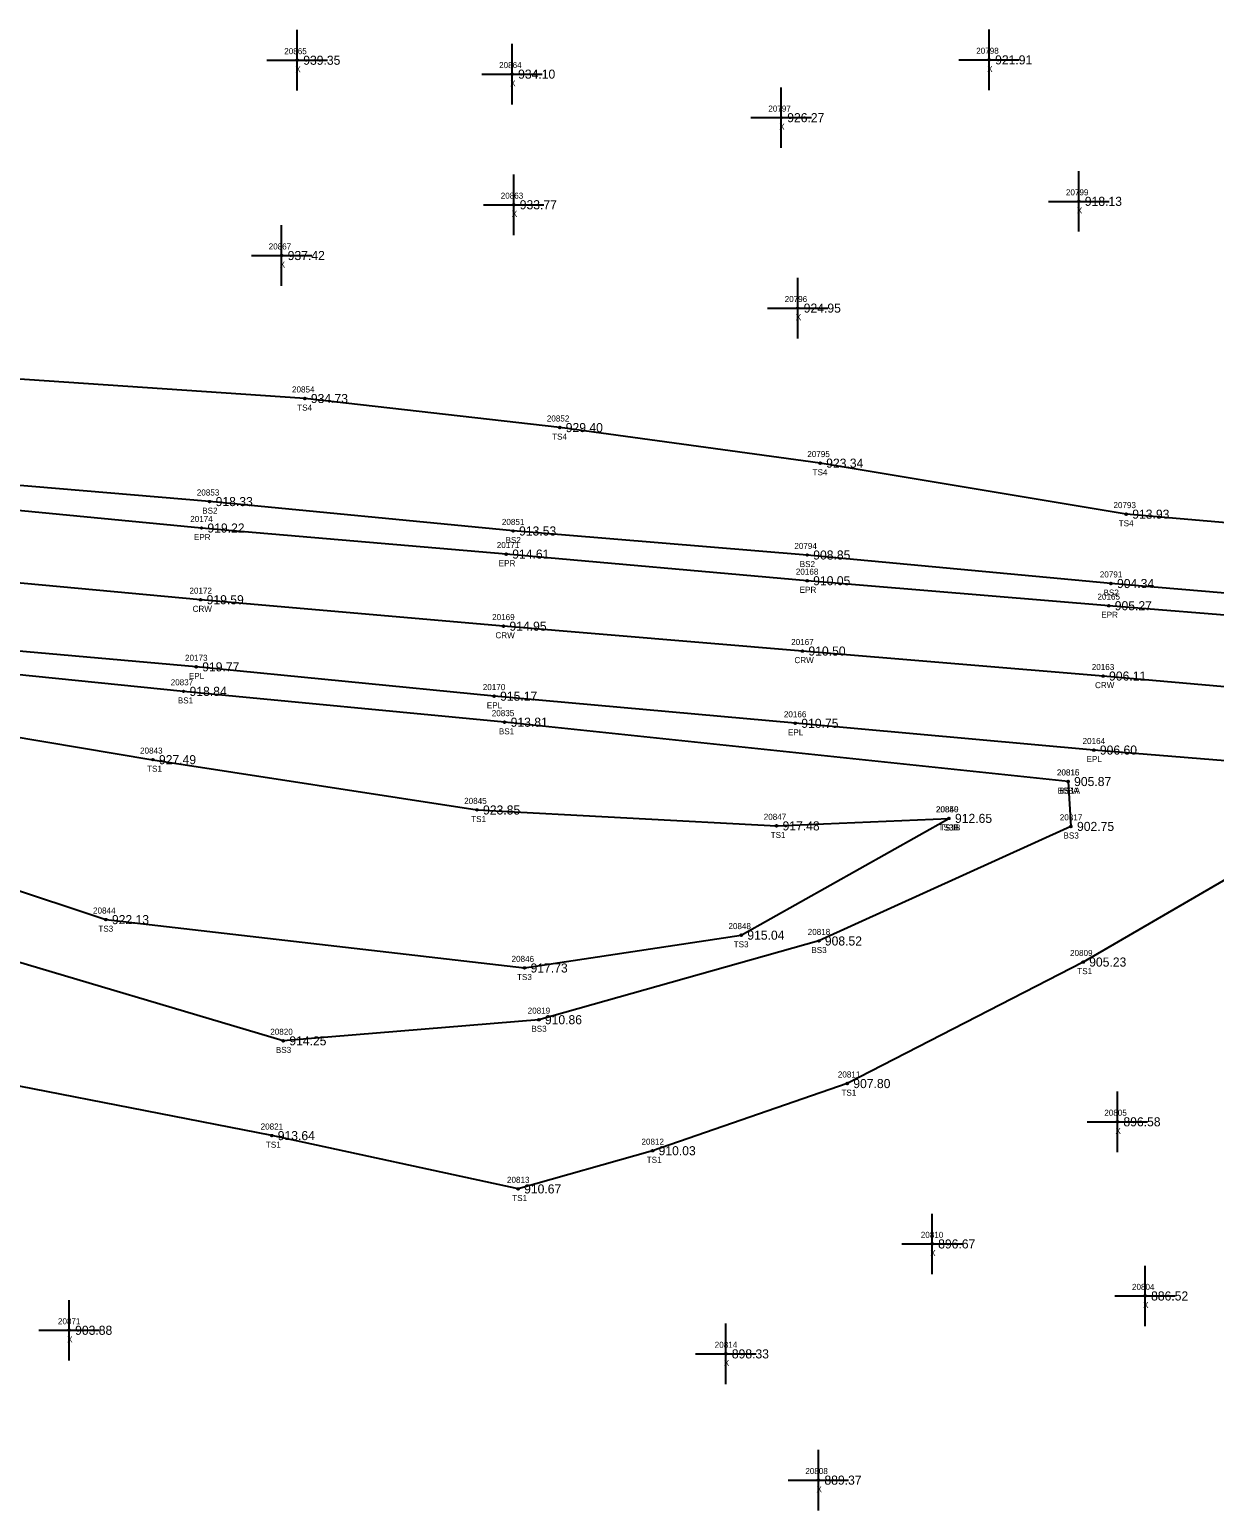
# Model space of a CAD drawing. Extents: x 1394668 to 1397182, y 1073212 to 1074501.
# Drawn here: x 1394844.2 to 1395039.9, y 1073234.9 to 1073479.6 of the extents above; entities that cross this region are included whole.
import ezdxf

# ---------------------------------------------------------------- set-up
doc = ezdxf.new("R2010")
doc.units = 0
for name, color, linetype in [('RD_DTM_BkLn1', 7, 'Continuous'), ('RD_DTM_BkLn2', 7, 'Continuous'), ('RD_DTM_BkLn_txCode', 7, 'Continuous'), ('RD_EX_Misc', 7, 'Continuous'), ('RD_EX_Misc_txCode', 7, 'Continuous'), ('RD_EX_Road', 7, 'Continuous'), ('RD_EX_Road_txCode', 7, 'Continuous'), ('RD_EX_TX_Misc_ELEV', 7, 'Continuous'), ('RD_EX_TX_Road_ELEV', 7, 'Continuous'), ('RD_HC_Survey_ELEV', 7, 'Continuous'), ('RD_HC_Survey_txCode', 7, 'Continuous'), ('RD_SMD_Locator', 7, 'Continuous')]:
    doc.layers.add(name, color=color, linetype=linetype)

msp = doc.modelspace()

# ---------------------------------------------------------------- linework, layer by layer
at = {"layer": 'RD_DTM_BkLn1'}
msp.add_lwpolyline([(1395269.86, 1073375.63), (1395220.56, 1073368.3), (1395170.5, 1073365.12), (1395120.93, 1073365.32), (1395071.05, 1073368.42), (1395021.54, 1073372.81), (1394971.87, 1073376.94), (1394922.47, 1073381.05), (1394872.44, 1073385.42), (1394823.01, 1073389.97), (1394773.09, 1073394.98), (1394723.98, 1073400.02), (1394673.96, 1073406.13)], dxfattribs=at)
at = {"layer": 'RD_DTM_BkLn2'}
for points in [[(1395114.77, 1073459.28), (1395092.12, 1073431.75), (1395067.87, 1073399.99), (1395061.04, 1073396.47), (1395025.37, 1073399.56), (1394974.8, 1073407.99), (1394931.77, 1073413.87), (1394889.66, 1073418.67), (1394830.32, 1073422.7), (1394776.13, 1073426.07), (1394727.84, 1073425.98), (1394677.73, 1073438.51)], [(1395071.67, 1073383.99), (1395022.85, 1073388.1), (1394972.66, 1073392.81), (1394924.06, 1073396.78), (1394873.93, 1073401.64), (1394823.64, 1073405.87), (1394773.54, 1073410.91), (1394725.43, 1073416.05), (1394673.91, 1073423.25)], [(1394670.94, 1073391.19), (1394739.49, 1073383.51), (1394739.49, 1073383.51), (1394765.8, 1073375.46), (1394810.45, 1073368.06), (1394864.56, 1073358.99), (1394918.11, 1073350.68), (1394967.59, 1073348.05), (1394996.08, 1073349.29)], [(1394739.49, 1073383.51), (1394764.94, 1073371.86), (1394804.66, 1073349.89), (1394856.79, 1073332.56), (1394925.96, 1073324.57), (1394961.77, 1073329.99), (1394996.08, 1073349.29)], [(1395015.76, 1073355.38), (1394922.67, 1073365.18), (1394869.62, 1073370.28), (1394820.24, 1073375.25), (1394747.09, 1073382.96)], [(1395065.07, 1073345.12), (1395048.86, 1073343.34), (1395018.25, 1073325.55), (1394979.28, 1073305.47), (1394947.11, 1073294.37), (1394924.89, 1073288.06), (1394884.19, 1073296.87), (1394821.51, 1073309.12), (1394774.98, 1073327.05), (1394739.84, 1073344.19), (1394711.9, 1073363.27), (1394701.45, 1073376.62)], [(1395015.76, 1073355.38), (1395016.24, 1073347.96), (1394974.58, 1073329.03), (1394928.32, 1073316.02), (1394886.1, 1073312.53), (1394835.64, 1073327.51), (1394785.59, 1073349.09), (1394745.24, 1073368.83), (1394701.45, 1073376.62)]]:
    msp.add_lwpolyline(points, dxfattribs=at)
at = {"layer": 'RD_EX_Misc'}
for p, q in [((1394888.4, 1073469.57), (1394888.4, 1073479.57)), ((1394923.9, 1073467.27), (1394923.9, 1073477.27)), ((1395002.71, 1073469.63), (1395002.71, 1073479.63)), ((1394883.4, 1073474.57), (1394893.4, 1073474.57)), ((1394997.71, 1073474.63), (1395007.71, 1073474.63)), ((1394918.9, 1073472.27), (1394928.9, 1073472.27)), ((1394968.36, 1073460.08), (1394968.36, 1073470.08)), ((1394963.36, 1073465.08), (1394973.36, 1073465.08)), ((1394924.17, 1073445.69), (1394924.17, 1073455.69)), ((1395017.53, 1073446.25), (1395017.53, 1073456.25)), ((1394919.17, 1073450.69), (1394929.17, 1073450.69)), ((1395012.53, 1073451.25), (1395022.53, 1073451.25)), ((1394885.83, 1073437.3), (1394885.83, 1073447.3)), ((1394880.83, 1073442.3), (1394890.83, 1073442.3)), ((1394971.09, 1073428.61), (1394971.09, 1073438.61)), ((1394966.09, 1073433.61), (1394976.09, 1073433.61)), ((1395023.91, 1073294.15), (1395023.91, 1073304.15)), ((1395018.91, 1073299.15), (1395028.91, 1073299.15)), ((1394993.3, 1073273.97), (1394993.3, 1073283.97)), ((1394988.3, 1073278.97), (1394998.3, 1073278.97)), ((1395028.48, 1073265.37), (1395028.48, 1073275.37)), ((1394850.71, 1073259.7), (1394850.71, 1073269.7)), ((1395023.48, 1073270.37), (1395033.48, 1073270.37)), ((1394845.71, 1073264.7), (1394855.71, 1073264.7)), ((1394959.21, 1073255.8), (1394959.21, 1073265.8)), ((1394954.21, 1073260.8), (1394964.21, 1073260.8)), ((1394974.51, 1073234.94), (1394974.51, 1073244.94)), ((1394969.51, 1073239.94), (1394979.51, 1073239.94))]:
    msp.add_line(p, q, dxfattribs=at)
at = {"layer": 'RD_EX_Road'}
for points in [[(1395267.16, 1073387.31), (1395218.96, 1073380.11), (1395169.59, 1073377.09), (1395120.52, 1073377.31), (1395071.75, 1073380.45), (1395022.48, 1073384.43), (1394972.65, 1073388.56), (1394922.93, 1073392.96), (1394872.57, 1073397.27), (1394823.93, 1073401.93), (1394774.03, 1073406.64), (1394724.37, 1073412.09), (1394676.23, 1073417.71)], [(1395271.04, 1073363.5), (1395222.14, 1073356.32), (1395170.34, 1073352.86), (1395119.91, 1073353.35), (1395070.19, 1073356.5), (1395020.02, 1073360.58), (1394970.69, 1073365), (1394920.93, 1073369.48), (1394871.71, 1073374.33), (1394821.21, 1073378.78), (1394772.49, 1073383.81), (1394722.62, 1073388.78), (1394672.88, 1073394.93)]]:
    msp.add_lwpolyline(points, dxfattribs=at)
at = {"layer": 'RD_SMD_Locator'}
for centre in [(1394888.4, 1073474.57), (1394923.9, 1073472.27), (1395002.71, 1073474.63), (1394968.36, 1073465.08), (1394924.17, 1073450.69), (1395017.53, 1073451.25), (1394885.83, 1073442.3), (1394971.09, 1073433.61), (1394889.66, 1073418.67), (1394931.77, 1073413.87), (1394974.8, 1073407.99), (1394873.93, 1073401.64), (1395025.37, 1073399.56), (1394872.57, 1073397.27), (1394924.06, 1073396.78), (1394922.93, 1073392.96), (1394972.66, 1073392.81), (1394972.65, 1073388.56), (1395022.85, 1073388.1), (1394872.44, 1073385.42), (1395022.48, 1073384.43), (1394922.47, 1073381.05), (1394971.87, 1073376.94), (1394871.71, 1073374.33), (1395021.54, 1073372.81), (1394869.62, 1073370.28), (1394920.93, 1073369.48), (1394922.67, 1073365.18), (1394970.69, 1073365), (1395020.02, 1073360.58), (1394864.56, 1073358.99), (1395015.76, 1073355.38), (1395015.76, 1073355.38), (1394918.11, 1073350.68), (1394967.59, 1073348.05), (1394996.08, 1073349.29), (1394996.08, 1073349.29), (1395016.24, 1073347.96), (1394856.79, 1073332.56), (1394961.77, 1073329.99), (1394974.58, 1073329.03), (1395018.25, 1073325.55), (1394925.96, 1073324.57), (1394928.32, 1073316.02), (1394886.1, 1073312.53), (1394979.28, 1073305.47), (1395023.91, 1073299.15), (1394884.19, 1073296.87), (1394947.11, 1073294.37), (1394924.89, 1073288.06), (1394993.3, 1073278.97), (1395028.48, 1073270.37), (1394850.71, 1073264.7), (1394959.21, 1073260.8), (1394974.51, 1073239.94)]:
    msp.add_circle(centre, 0.15, dxfattribs=at)

# ---------------------------------------------------------------- texts
at = {"layer": 'RD_DTM_BkLn_txCode'}
for s, p in [('20854', (1394887.54, 1073419.67)), ('TS4', (1394888.41, 1073416.67)), ('20852', (1394929.65, 1073414.87)), ('TS4', (1394930.52, 1073411.87)), ('20795', (1394972.68, 1073408.99)), ('TS4', (1394973.56, 1073405.99)), ('20853', (1394871.82, 1073402.64)), ('20793', (1395023.26, 1073400.56)), ('BS2', (1394872.71, 1073399.64)), ('20851', (1394922.22, 1073397.78)), ('TS4', (1395024.13, 1073397.56)), ('BS2', (1394922.83, 1073394.78)), ('20794', (1394970.54, 1073393.81)), ('BS2', (1394971.43, 1073390.81)), ('20791', (1395021.01, 1073389.1)), ('BS2', (1395021.62, 1073386.1)), ('20837', (1394867.5, 1073371.28)), ('BS1', (1394868.68, 1073368.28)), ('20835', (1394920.55, 1073366.18)), ('BS1', (1394921.72, 1073363.18)), ('20843', (1394862.44, 1073359.99)), ('TS1', (1394863.6, 1073356.99)), ('20816', (1395013.91, 1073356.38)), ('20815', (1395013.93, 1073356.38)), ('20845', (1394915.99, 1073351.68)), ('BS3A', (1395014.05, 1073353.38)), ('BS1A', (1395014.33, 1073353.38)), ('20847', (1394965.48, 1073349.05)), ('20850', (1394993.92, 1073350.29)), ('20849', (1394993.96, 1073350.29)), ('TS1', (1394917.15, 1073348.68)), ('TS3B', (1394994.37, 1073347.29)), ('TS1B', (1394994.65, 1073347.29)), ('20817', (1395014.4, 1073348.96)), ('TS1', (1394966.63, 1073346.05)), ('BS3', (1395015.01, 1073345.96)), ('20844', (1394854.67, 1073333.56)), ('TS3', (1394855.55, 1073330.56)), ('20848', (1394959.65, 1073330.99)), ('20818', (1394972.75, 1073330.03)), ('TS3', (1394960.52, 1073327.99)), ('BS3', (1394973.35, 1073327.03)), ('20846', (1394923.82, 1073325.57)), ('20809', (1395016.09, 1073326.55)), ('TS3', (1394924.72, 1073322.57)), ('TS1', (1395017.29, 1073323.55)), ('20819', (1394926.48, 1073317.02)), ('20820', (1394883.95, 1073313.53)), ('BS3', (1394927.09, 1073314.02)), ('BS3', (1394884.88, 1073310.53)), ('20811', (1394977.73, 1073306.47)), ('TS1', (1394978.32, 1073303.47)), ('20821', (1394882.36, 1073297.87)), ('20812', (1394945.28, 1073295.37)), ('TS1', (1394883.23, 1073294.87)), ('TS1', (1394946.15, 1073292.37)), ('20813', (1394923.06, 1073289.06)), ('TS1', (1394923.93, 1073286.06))]:
    msp.add_text(s, height=1, dxfattribs=at).set_placement(p)
at = {"layer": 'RD_EX_Misc_txCode'}
for s, p in [('20865', (1394886.26, 1073475.57)), ('20798', (1395000.59, 1073475.63)), ('X', (1394888.09, 1073472.57)), ('20864', (1394921.76, 1073473.27)), ('X', (1395002.4, 1073472.63)), ('X', (1394923.59, 1073470.27)), ('20797', (1394966.24, 1073466.08)), ('X', (1394968.04, 1073463.08)), ('20799', (1395015.41, 1073452.25)), ('20863', (1394922.03, 1073451.69)), ('X', (1394923.85, 1073448.69)), ('X', (1395017.21, 1073449.25)), ('20867', (1394883.69, 1073443.3)), ('X', (1394885.51, 1073440.3)), ('20796', (1394968.94, 1073434.61)), ('X', (1394970.77, 1073431.61)), ('20805', (1395021.75, 1073300.15)), ('X', (1395023.59, 1073297.15)), ('20810', (1394991.43, 1073279.97)), ('X', (1394992.99, 1073276.97)), ('20804', (1395026.32, 1073271.37)), ('X', (1395028.16, 1073268.37)), ('20871', (1394848.87, 1073265.7)), ('X', (1394850.39, 1073262.7)), ('20814', (1394957.38, 1073261.8)), ('X', (1394958.9, 1073258.8)), ('20808', (1394972.35, 1073240.94)), ('X', (1394974.2, 1073237.94))]:
    msp.add_text(s, height=1, dxfattribs=at).set_placement(p)
at = {"layer": 'RD_EX_Road_txCode'}
for s, p in [('20174', (1394870.73, 1073398.27)), ('EPR', (1394871.34, 1073395.27)), ('20171', (1394921.38, 1073393.96)), ('EPR', (1394921.7, 1073390.96)), ('20168', (1394970.79, 1073389.56)), ('EPR', (1394971.42, 1073386.56)), ('20165', (1395020.62, 1073385.43)), ('EPR', (1395021.25, 1073382.43)), ('20173', (1394869.87, 1073375.33)), ('EPL', (1394870.5, 1073372.33)), ('20170', (1394919.06, 1073370.48)), ('EPL', (1394919.73, 1073367.48)), ('20166', (1394968.81, 1073366)), ('EPL', (1394969.49, 1073363)), ('20164', (1395018.16, 1073361.58)), ('EPL', (1395018.81, 1073358.58))]:
    msp.add_text(s, height=1, dxfattribs=at).set_placement(p)
at = {"layer": 'RD_EX_TX_Misc_ELEV'}
for s, p in [('939.35', (1394889.4, 1073473.82)), ('921.91', (1395003.71, 1073473.88)), ('934.10', (1394924.9, 1073471.52)), ('926.27', (1394969.36, 1073464.33)), ('933.77', (1394925.17, 1073449.94)), ('918.13', (1395018.53, 1073450.5)), ('937.42', (1394886.83, 1073441.55)), ('924.95', (1394972.09, 1073432.86)), ('934.73', (1394890.66, 1073417.92)), ('929.40', (1394932.77, 1073413.12)), ('923.34', (1394975.8, 1073407.24)), ('918.33', (1394874.93, 1073400.89)), ('913.93', (1395026.37, 1073398.81)), ('913.53', (1394925.06, 1073396.03)), ('908.85', (1394973.66, 1073392.06)), ('904.34', (1395023.85, 1073387.35)), ('918.84', (1394870.62, 1073369.53)), ('913.81', (1394923.67, 1073364.43)), ('927.49', (1394865.56, 1073358.24)), ('905.87', (1395016.76, 1073354.63)), ('905.87', (1395016.76, 1073354.63)), ('923.85', (1394919.11, 1073349.93)), ('912.65', (1394997.08, 1073348.54)), ('912.65', (1394997.08, 1073348.54)), ('917.48', (1394968.59, 1073347.3)), ('902.75', (1395017.24, 1073347.21)), ('922.13', (1394857.79, 1073331.81)), ('915.04', (1394962.77, 1073329.24)), ('908.52', (1394975.58, 1073328.28)), ('905.23', (1395019.25, 1073324.8)), ('917.73', (1394926.96, 1073323.82)), ('910.86', (1394929.32, 1073315.27)), ('914.25', (1394887.1, 1073311.78)), ('907.80', (1394980.28, 1073304.72)), ('896.58', (1395024.91, 1073298.4)), ('913.64', (1394885.19, 1073296.12)), ('910.03', (1394948.11, 1073293.62)), ('910.67', (1394925.89, 1073287.31)), ('896.67', (1394994.3, 1073278.22)), ('886.52', (1395029.48, 1073269.62)), ('903.88', (1394851.71, 1073263.95)), ('898.33', (1394960.21, 1073260.05)), ('889.37', (1394975.51, 1073239.19))]:
    msp.add_text(s, height=1.5, dxfattribs=at).set_placement(p)
at = {"layer": 'RD_EX_TX_Road_ELEV'}
for s, p in [('919.22', (1394873.57, 1073396.52)), ('914.61', (1394923.93, 1073392.21)), ('910.05', (1394973.65, 1073387.81)), ('905.27', (1395023.48, 1073383.68)), ('919.77', (1394872.71, 1073373.58)), ('915.17', (1394921.93, 1073368.73)), ('910.75', (1394971.69, 1073364.25)), ('906.60', (1395021.02, 1073359.83))]:
    msp.add_text(s, height=1.5, dxfattribs=at).set_placement(p)
at = {"layer": 'RD_HC_Survey_ELEV'}
for s, p in [('919.59', (1394873.44, 1073384.67)), ('914.95', (1394923.47, 1073380.3)), ('910.50', (1394972.87, 1073376.19)), ('906.11', (1395022.54, 1073372.06))]:
    msp.add_text(s, height=1.5, dxfattribs=at).set_placement(p)
at = {"layer": 'RD_HC_Survey_txCode'}
for s, p in [('20172', (1394870.6, 1073386.42)), ('CRW', (1394871.12, 1073383.42)), ('20169', (1394920.61, 1073382.05)), ('CRW', (1394921.16, 1073379.05)), ('20167', (1394970.02, 1073377.94)), ('CRW', (1394970.56, 1073374.94)), ('20163', (1395019.68, 1073373.81)), ('CRW', (1395020.22, 1073370.81))]:
    msp.add_text(s, height=1, dxfattribs=at).set_placement(p)

doc.saveas('drawing.dxf')
